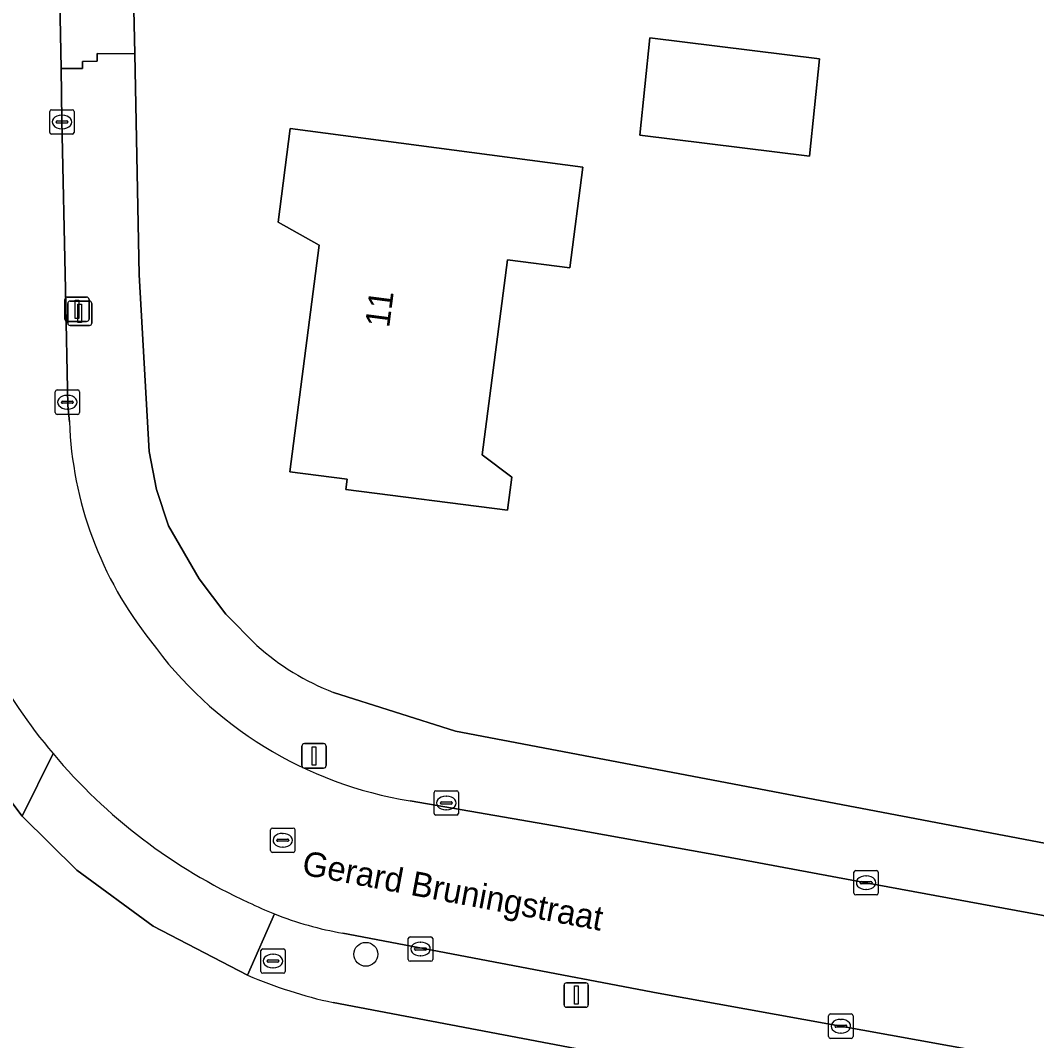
# Model space of a CAD drawing. Extents: x 161258 to 161838, y 380833 to 381727.
# Drawn here: x 161655.94 to 161697.58, y 381153.12 to 381194.91 of the extents above; entities that cross this region are included whole.
import ezdxf

# ---------------------------------------------------------------- set-up
doc = ezdxf.new("R2010")
doc.units = 0
for name, color, linetype in [('IMGEO_Boom', 7, 'Continuous'), ('IMGEO_Brandkraan', 7, 'Continuous'), ('IMGEO_Erf', 7, 'Continuous'), ('IMGEO_Kolk', 7, 'Continuous'), ('IMGEO_Lichtmast', 7, 'Continuous'), ('IMGEO_Openbare_ruimte_label', 7, 'Continuous'), ('IMGEO_Pand', 7, 'Continuous'), ('IMGEO_Pand_nummerreeks', 7, 'Continuous'), ('IMGEO_Rijbaan_lokaal_open', 7, 'Continuous'), ('IMGEO_Rioolput', 7, 'Continuous'), ('IMGEO_Voetpad_open', 7, 'Continuous')]:
    doc.layers.add(name, color=color, linetype=linetype)

msp = doc.modelspace()

# ---------------------------------------------------------------- linework, layer by layer
at = {"layer": 'IMGEO_Boom'}
msp.add_circle((161670.093, 381156.658), 0.489, dxfattribs=at)
at = {"layer": 'IMGEO_Brandkraan'}
for p, q in [((161665.79, 381155.956), (161665.79, 381156.808)), ((161665.865, 381156.882), (161666.717, 381156.882)), ((161666.278, 381156.662), (161666.303, 381156.662)), ((161666.791, 381156.808), (161666.791, 381155.956)), ((161666.049, 381156.376), (161666.049, 381156.388)), ((161666.487, 381156.339), (161666.089, 381156.339)), ((161666.092, 381156.425), (161666.49, 381156.425)), ((161666.533, 381156.388), (161666.533, 381156.376)), ((161666.717, 381155.882), (161665.865, 381155.882)), ((161666.301, 381156.102), (161666.276, 381156.102))]:
    msp.add_line(p, q, dxfattribs=at)
for points in [[(161665.79, 381155.956), (161665.79, 381156.808)], [(161665.865, 381156.882), (161666.717, 381156.882)], [(161666.791, 381156.808), (161666.791, 381155.956)], [(161666.717, 381155.882), (161665.865, 381155.882)]]:
    msp.add_lwpolyline(points, dxfattribs=at)
for centre, radius, start, end in [((161665.867, 381156.806), 0.0765, 91.552, 178.448), ((161665.867, 381156.806), 0.0765, 91.552, 178.448), ((161666.715, 381156.806), 0.0765, 1.552, 88.448), ((161666.715, 381156.806), 0.0765, 1.552, 88.448), ((161666.089, 381156.385), 0.0403, 85.8775, 175.7526), ((161666.086, 381156.375), 0.0366, 178.938, 274.7102), ((161666.49, 381156.382), 0.043, 264.8664, 352.4533), ((161666.494, 381156.387), 0.0386, 1.7309, 96.639), ((161665.867, 381155.958), 0.0765, 181.552, 268.448), ((161665.867, 381155.958), 0.0765, 181.552, 268.448), ((161666.715, 381155.958), 0.0765, 271.552, 358.448), ((161666.715, 381155.958), 0.0765, 271.552, 358.448)]:
    msp.add_arc(centre, radius, start, end, dxfattribs=at)
for centre, major_axis, ratio, start_param, end_param in [((161666.277, 381156.382), (-0.387, 0.002), 0.722429, 4.712389, 7.853982), ((161666.302, 381156.382), (-0.39, 0.002), 0.717154, 1.570796, 4.712389)]:
    msp.add_ellipse(centre, major_axis=major_axis, ratio=ratio, start_param=start_param, end_param=end_param, dxfattribs=at)
at = {"layer": 'IMGEO_Erf'}
for points in [[(161668.77, 381167.385), (161673.77, 381165.793), (161737.053, 381153.773), (161737.441, 381153.699), (161737.997, 381153.598), (161738.112, 381154.157), (161737.938, 381154.198), (161753.579, 381238.309), (161753.673, 381238.82), (161753.349, 381239.081), (161753.133, 381238.804), (161751.742, 381240.033), (161751.586, 381239.216), (161750.481, 381239.459), (161750.713, 381240.543), (161751.212, 381243.492), (161751.454, 381244.596), (161752.571, 381244.423), (161752.507, 381243.755), (161754.157, 381244.071), (161754.273, 381243.898), (161754.635, 381244.025), (161769.385, 381323.827)], [(161660.762, 381266.569), (161660.073, 381256.315), (161659.92, 381252.625), (161659.847, 381249.958), (161659.857, 381232.624), (161660.002, 381225.178), (161660.058, 381222.332), (161660.56, 381196.578), (161660.619, 381193.545), (161660.796, 381184.49), (161661.214, 381177.248), (161661.514, 381175.703), (161662, 381174.206), (161663.26, 381172.033), (161664.355, 381170.597), (161665.625, 381169.313)], [(161665.248, 381155.803), (161661.37, 381157.812), (161658.243, 381160.102), (161656.002, 381162.313), (161653.21, 381166.017)], [(161729.059, 381143.246), (161705.296, 381147.752), (161698.258, 381149.087), (161668.75, 381154.683)]]:
    msp.add_lwpolyline(points, dxfattribs=at)
for points in [[(161688.68, 381193.336), (161688.275, 381189.356), (161681.327, 381190.217), (161681.732, 381194.198)], [(161675.903, 381174.848), (161669.271, 381175.703), (161669.325, 381176.122), (161666.982, 381176.424), (161668.179, 381185.701), (161666.501, 381186.645), (161666.996, 381190.479), (161678.986, 381188.902), (161678.453, 381184.77), (161675.892, 381185.1), (161674.863, 381177.122), (161676.077, 381176.196)]]:
    msp.add_lwpolyline(points, close=True, dxfattribs=at)
for centre, radius, start, end in [((161672.457, 381176.928), 10.23, 228.1033, 248.877), ((161672.604, 381172.77), 18.493, 246.5596, 257.97)]:
    msp.add_arc(centre, radius, start, end, dxfattribs=at)
at = {"layer": 'IMGEO_Kolk'}
for p, q in [((161657.138, 381190.326), (161657.138, 381191.178)), ((161657.213, 381191.252), (161658.065, 381191.252)), ((161657.626, 381191.032), (161657.651, 381191.032)), ((161658.139, 381191.178), (161658.139, 381190.326)), ((161657.397, 381190.746), (161657.397, 381190.758)), ((161657.835, 381190.709), (161657.437, 381190.709)), ((161657.44, 381190.795), (161657.838, 381190.795)), ((161657.881, 381190.758), (161657.881, 381190.746)), ((161658.065, 381190.252), (161657.213, 381190.252)), ((161657.649, 381190.472), (161657.624, 381190.472)), ((161657.361, 381178.847), (161657.361, 381179.699)), ((161657.436, 381179.773), (161658.288, 381179.773)), ((161658.362, 381179.699), (161658.362, 381178.847)), ((161657.62, 381179.267), (161657.62, 381179.279)), ((161658.058, 381179.23), (161657.66, 381179.23)), ((161657.663, 381179.316), (161658.061, 381179.316)), ((161657.849, 381179.553), (161657.874, 381179.553)), ((161658.104, 381179.279), (161658.104, 381179.267)), ((161657.872, 381178.993), (161657.847, 381178.993)), ((161658.288, 381178.773), (161657.436, 381178.773)), ((161672.965, 381163.357), (161673.817, 381163.357)), ((161672.89, 381162.431), (161672.89, 381163.283)), ((161673.378, 381163.137), (161673.403, 381163.137)), ((161673.891, 381163.283), (161673.891, 381162.431)), ((161673.149, 381162.851), (161673.149, 381162.863)), ((161673.587, 381162.814), (161673.189, 381162.814)), ((161673.192, 381162.9), (161673.59, 381162.9)), ((161673.401, 381162.577), (161673.376, 381162.577)), ((161673.633, 381162.863), (161673.633, 381162.851)), ((161673.817, 381162.357), (161672.965, 381162.357)), ((161690.094, 381159.165), (161690.094, 381160.017)), ((161690.169, 381160.091), (161691.021, 381160.091)), ((161691.095, 381160.017), (161691.095, 381159.165)), ((161690.353, 381159.585), (161690.353, 381159.597)), ((161690.396, 381159.634), (161690.794, 381159.634)), ((161690.582, 381159.871), (161690.607, 381159.871)), ((161690.837, 381159.597), (161690.837, 381159.585)), ((161690.791, 381159.548), (161690.393, 381159.548)), ((161690.605, 381159.311), (161690.58, 381159.311)), ((161691.021, 381159.091), (161690.169, 381159.091)), ((161671.833, 381156.448), (161671.833, 381157.3)), ((161671.908, 381157.374), (161672.76, 381157.374)), ((161672.321, 381157.154), (161672.346, 381157.154)), ((161672.834, 381157.3), (161672.834, 381156.448)), ((161672.092, 381156.868), (161672.092, 381156.88)), ((161672.53, 381156.831), (161672.132, 381156.831)), ((161672.135, 381156.917), (161672.533, 381156.917)), ((161672.576, 381156.88), (161672.576, 381156.868)), ((161672.76, 381156.374), (161671.908, 381156.374)), ((161672.344, 381156.594), (161672.319, 381156.594)), ((161689.134, 381154.214), (161689.986, 381154.214)), ((161689.059, 381153.288), (161689.059, 381154.14)), ((161689.361, 381153.757), (161689.759, 381153.757)), ((161689.547, 381153.994), (161689.572, 381153.994)), ((161690.06, 381154.14), (161690.06, 381153.288)), ((161689.318, 381153.708), (161689.318, 381153.72)), ((161689.756, 381153.671), (161689.358, 381153.671)), ((161689.57, 381153.434), (161689.545, 381153.434)), ((161689.802, 381153.72), (161689.802, 381153.708)), ((161689.986, 381153.214), (161689.134, 381153.214))]:
    msp.add_line(p, q, dxfattribs=at)
for points in [[(161657.138, 381190.326), (161657.138, 381191.178)], [(161657.213, 381191.252), (161658.065, 381191.252)], [(161658.139, 381191.178), (161658.139, 381190.326)], [(161658.065, 381190.252), (161657.213, 381190.252)], [(161657.361, 381178.847), (161657.361, 381179.699)], [(161657.436, 381179.773), (161658.288, 381179.773)], [(161658.362, 381179.699), (161658.362, 381178.847)], [(161658.288, 381178.773), (161657.436, 381178.773)], [(161672.965, 381163.357), (161673.817, 381163.357)], [(161672.89, 381162.431), (161672.89, 381163.283)], [(161673.891, 381163.283), (161673.891, 381162.431)], [(161673.817, 381162.357), (161672.965, 381162.357)], [(161690.094, 381159.165), (161690.094, 381160.017)], [(161690.169, 381160.091), (161691.021, 381160.091)], [(161691.095, 381160.017), (161691.095, 381159.165)], [(161691.021, 381159.091), (161690.169, 381159.091)], [(161671.833, 381156.448), (161671.833, 381157.3)], [(161671.908, 381157.374), (161672.76, 381157.374)], [(161672.834, 381157.3), (161672.834, 381156.448)], [(161672.76, 381156.374), (161671.908, 381156.374)], [(161689.134, 381154.214), (161689.986, 381154.214)], [(161689.059, 381153.288), (161689.059, 381154.14)], [(161690.06, 381154.14), (161690.06, 381153.288)], [(161689.986, 381153.214), (161689.134, 381153.214)]]:
    msp.add_lwpolyline(points, dxfattribs=at)
for centre, radius, start, end in [((161657.215, 381191.176), 0.0765, 91.552, 178.448), ((161657.215, 381191.176), 0.0765, 91.552, 178.448), ((161658.063, 381191.176), 0.0765, 1.552, 88.448), ((161658.063, 381191.176), 0.0765, 1.552, 88.448), ((161657.437, 381190.755), 0.0403, 85.8775, 175.7526), ((161657.434, 381190.745), 0.0366, 178.938, 274.7102), ((161657.838, 381190.752), 0.043, 264.8664, 352.4533), ((161657.842, 381190.757), 0.0386, 1.7309, 96.639), ((161657.215, 381190.328), 0.0765, 181.552, 268.448), ((161657.215, 381190.328), 0.0765, 181.552, 268.448), ((161658.063, 381190.328), 0.0765, 271.552, 358.448), ((161658.063, 381190.328), 0.0765, 271.552, 358.448), ((161657.438, 381179.697), 0.0765, 91.552, 178.448), ((161657.438, 381179.697), 0.0765, 91.552, 178.448), ((161658.286, 381179.697), 0.0765, 1.552, 88.448), ((161658.286, 381179.697), 0.0765, 1.552, 88.448), ((161657.66, 381179.276), 0.0403, 85.8775, 175.7526), ((161657.657, 381179.266), 0.0366, 178.938, 274.7102), ((161658.061, 381179.273), 0.043, 264.8664, 352.4533), ((161658.065, 381179.278), 0.0386, 1.7309, 96.639), ((161657.438, 381178.849), 0.0765, 181.552, 268.448), ((161657.438, 381178.849), 0.0765, 181.552, 268.448), ((161658.286, 381178.849), 0.0765, 271.552, 358.448), ((161658.286, 381178.849), 0.0765, 271.552, 358.448), ((161672.967, 381163.281), 0.0765, 91.552, 178.448), ((161672.967, 381163.281), 0.0765, 91.552, 178.448), ((161673.815, 381163.281), 0.0765, 1.552, 88.448), ((161673.815, 381163.281), 0.0765, 1.552, 88.448), ((161673.189, 381162.86), 0.0403, 85.8775, 175.7526), ((161673.186, 381162.85), 0.0366, 178.938, 274.7102), ((161673.59, 381162.857), 0.043, 264.8664, 352.4533), ((161673.594, 381162.862), 0.0386, 1.7309, 96.639), ((161672.967, 381162.433), 0.0765, 181.552, 268.448), ((161672.967, 381162.433), 0.0765, 181.552, 268.448), ((161673.815, 381162.433), 0.0765, 271.552, 358.448), ((161673.815, 381162.433), 0.0765, 271.552, 358.448), ((161690.171, 381160.015), 0.0765, 91.552, 178.448), ((161690.171, 381160.015), 0.0765, 91.552, 178.448), ((161691.019, 381160.015), 0.0765, 1.552, 88.448), ((161691.019, 381160.015), 0.0765, 1.552, 88.448), ((161690.393, 381159.594), 0.0403, 85.8775, 175.7526), ((161690.39, 381159.584), 0.0366, 178.938, 274.7102), ((161690.794, 381159.591), 0.043, 264.8664, 352.4533), ((161690.798, 381159.596), 0.0386, 1.7309, 96.639), ((161690.171, 381159.167), 0.0765, 181.552, 268.448), ((161690.171, 381159.167), 0.0765, 181.552, 268.448), ((161691.019, 381159.167), 0.0765, 271.552, 358.448), ((161691.019, 381159.167), 0.0765, 271.552, 358.448), ((161671.91, 381157.298), 0.0765, 91.552, 178.448), ((161671.91, 381157.298), 0.0765, 91.552, 178.448), ((161672.758, 381157.298), 0.0765, 1.552, 88.448), ((161672.758, 381157.298), 0.0765, 1.552, 88.448), ((161672.132, 381156.877), 0.0403, 85.8775, 175.7526), ((161672.129, 381156.867), 0.0366, 178.938, 274.7102), ((161672.533, 381156.874), 0.043, 264.8664, 352.4533), ((161672.537, 381156.879), 0.0386, 1.7309, 96.639), ((161671.91, 381156.45), 0.0765, 181.552, 268.448), ((161671.91, 381156.45), 0.0765, 181.552, 268.448), ((161672.758, 381156.45), 0.0765, 271.552, 358.448), ((161672.758, 381156.45), 0.0765, 271.552, 358.448), ((161689.136, 381154.138), 0.0765, 91.552, 178.448), ((161689.136, 381154.138), 0.0765, 91.552, 178.448), ((161689.984, 381154.138), 0.0765, 1.552, 88.448), ((161689.984, 381154.138), 0.0765, 1.552, 88.448), ((161689.358, 381153.717), 0.0403, 85.8775, 175.7526), ((161689.763, 381153.719), 0.0386, 1.7309, 96.639), ((161689.355, 381153.707), 0.0366, 178.938, 274.7102), ((161689.759, 381153.714), 0.043, 264.8664, 352.4533), ((161689.136, 381153.29), 0.0765, 181.552, 268.448), ((161689.136, 381153.29), 0.0765, 181.552, 268.448), ((161689.984, 381153.29), 0.0765, 271.552, 358.448), ((161689.984, 381153.29), 0.0765, 271.552, 358.448)]:
    msp.add_arc(centre, radius, start, end, dxfattribs=at)
for centre, major_axis, ratio, start_param, end_param in [((161657.625, 381190.752), (-0.387, 0.002), 0.722429, 4.712389, 7.853982), ((161657.65, 381190.752), (-0.39, 0.002), 0.717154, 1.570796, 4.712389), ((161657.848, 381179.273), (-0.387, 0.002), 0.722429, 4.712389, 7.853982), ((161657.873, 381179.273), (-0.39, 0.002), 0.717154, 1.570796, 4.712389), ((161673.377, 381162.857), (-0.387, 0.002), 0.722429, 4.712389, 7.853982), ((161673.402, 381162.857), (-0.39, 0.002), 0.717154, 1.570796, 4.712389), ((161690.581, 381159.591), (-0.387, 0.002), 0.722429, 4.712389, 7.853982), ((161690.606, 381159.591), (-0.39, 0.002), 0.717154, 1.570796, 4.712389), ((161672.32, 381156.874), (-0.387, 0.002), 0.722429, 4.712389, 7.853982), ((161672.345, 381156.874), (-0.39, 0.002), 0.717154, 1.570796, 4.712389), ((161689.546, 381153.714), (-0.387, 0.002), 0.722429, 4.712389, 7.853982), ((161689.571, 381153.714), (-0.39, 0.002), 0.717154, 1.570796, 4.712389)]:
    msp.add_ellipse(centre, major_axis=major_axis, ratio=ratio, start_param=start_param, end_param=end_param, dxfattribs=at)
at = {"layer": 'IMGEO_Lichtmast'}
for p, q in [((161657.757, 381182.678), (161657.757, 381183.478)), ((161657.757, 381183.478), (161657.757, 381182.678)), ((161657.857, 381183.578), (161658.647, 381183.578)), ((161658.647, 381183.578), (161657.857, 381183.578)), ((161657.973, 381183.414), (161658.763, 381183.414)), ((161658.763, 381183.414), (161657.973, 381183.414)), ((161658.747, 381183.478), (161658.747, 381182.678)), ((161658.747, 381182.678), (161658.747, 381183.478)), ((161657.873, 381182.514), (161657.873, 381183.314)), ((161657.873, 381183.314), (161657.873, 381182.514)), ((161658.863, 381183.314), (161658.863, 381182.514)), ((161658.863, 381182.514), (161658.863, 381183.314)), ((161658.647, 381182.578), (161657.857, 381182.578)), ((161657.857, 381182.578), (161658.647, 381182.578)), ((161658.763, 381182.414), (161657.973, 381182.414)), ((161657.973, 381182.414), (161658.763, 381182.414)), ((161667.472, 381164.387), (161667.472, 381165.187)), ((161667.472, 381165.187), (161667.472, 381164.387)), ((161667.572, 381165.287), (161668.362, 381165.287)), ((161668.362, 381165.287), (161667.572, 381165.287)), ((161668.462, 381165.187), (161668.462, 381164.387)), ((161668.462, 381164.387), (161668.462, 381165.187)), ((161668.362, 381164.287), (161667.572, 381164.287)), ((161667.572, 381164.287), (161668.362, 381164.287)), ((161678.319, 381155.49), (161679.109, 381155.49)), ((161679.109, 381155.49), (161678.319, 381155.49)), ((161678.219, 381154.59), (161678.219, 381155.39)), ((161678.219, 381155.39), (161678.219, 381154.59)), ((161679.209, 381155.39), (161679.209, 381154.59)), ((161679.209, 381154.59), (161679.209, 381155.39)), ((161679.109, 381154.49), (161678.319, 381154.49)), ((161678.319, 381154.49), (161679.109, 381154.49))]:
    msp.add_line(p, q, dxfattribs=at)
for points in [[(161658.177, 381183.453), (161658.327, 381183.453), (161658.327, 381182.703), (161658.177, 381182.703), (161658.177, 381183.453)], [(161658.293, 381183.289), (161658.443, 381183.289), (161658.443, 381182.539), (161658.293, 381182.539), (161658.293, 381183.289)], [(161667.892, 381165.162), (161668.042, 381165.162), (161668.042, 381164.412), (161667.892, 381164.412), (161667.892, 381165.162)], [(161678.639, 381155.365), (161678.789, 381155.365), (161678.789, 381154.615), (161678.639, 381154.615), (161678.639, 381155.365)]]:
    msp.add_lwpolyline(points, dxfattribs=at)
for centre, start, end in [((161657.857, 381183.478), 90, 180), ((161657.857, 381183.478), 90, 180), ((161657.973, 381183.314), 90, 180), ((161657.973, 381183.314), 90, 180), ((161658.647, 381183.478), 0, 90), ((161658.647, 381183.478), 360, 90), ((161658.763, 381183.314), 0, 90), ((161658.763, 381183.314), 360, 90), ((161657.857, 381182.678), 180, 270), ((161657.857, 381182.678), 180, 270), ((161658.647, 381182.678), 270, 0), ((161658.647, 381182.678), 270, 0), ((161657.973, 381182.514), 180, 270), ((161657.973, 381182.514), 180, 270), ((161658.763, 381182.514), 270, 0), ((161658.763, 381182.514), 270, 0), ((161667.572, 381165.187), 90, 180), ((161667.572, 381165.187), 90, 180), ((161668.362, 381165.187), 0, 90), ((161668.362, 381165.187), 360, 90), ((161667.572, 381164.387), 180, 270), ((161667.572, 381164.387), 180, 270), ((161668.362, 381164.387), 270, 0), ((161668.362, 381164.387), 270, 0), ((161678.319, 381155.39), 90, 180), ((161678.319, 381155.39), 90, 180), ((161679.109, 381155.39), 0, 90), ((161679.109, 381155.39), 360, 90), ((161678.319, 381154.59), 180, 270), ((161678.319, 381154.59), 180, 270), ((161679.109, 381154.59), 270, 0), ((161679.109, 381154.59), 270, 0)]:
    msp.add_arc(centre, 0.1, start, end, dxfattribs=at)
at = {"layer": 'IMGEO_Pand'}
for points in [[(161681.732, 381194.198), (161681.327, 381190.217), (161688.275, 381189.356), (161688.68, 381193.336)], [(161675.903, 381174.848), (161676.077, 381176.196), (161674.863, 381177.122), (161675.892, 381185.1), (161678.453, 381184.77), (161678.986, 381188.902), (161666.996, 381190.479), (161666.501, 381186.645), (161668.179, 381185.701), (161666.982, 381176.424), (161669.325, 381176.122), (161669.271, 381175.703)]]:
    msp.add_lwpolyline(points, close=True, dxfattribs=at)
at = {"layer": 'IMGEO_Rijbaan_lokaal_open'}
for points in [[(161657.941, 381178.467), (161657.878, 381179.14), (161657.784, 381183.884), (161657.637, 381190.821), (161657.6, 381192.937), (161657.527, 381197.132), (161657.496, 381198.896), (161657.016, 381221.388), (161656.949, 381224.532), (161656.9, 381226.01), (161656.661, 381233.168), (161656.633, 381235.807), (161656.639, 381237.026), (161656.634, 381242.223), (161656.651, 381245.83), (161656.712, 381249.982), (161656.8, 381253.735)], [(161669.154, 381157.523), (161682.076, 381155.063), (161697.566, 381152.273), (161698.283, 381152.136), (161706.149, 381150.632), (161710.948, 381149.714), (161728.168, 381146.455), (161735.396, 381145.088), (161735.76, 381147.064), (161736.147, 381148.935), (161736.521, 381150.931), (161729.309, 381152.304), (161712.607, 381155.438), (161707.169, 381156.459), (161706.789, 381156.53), (161698.673, 381158.104), (161690.593, 381159.591), (161684.811, 381160.667), (161677.82, 381161.927), (161671.905, 381162.945)]]:
    msp.add_lwpolyline(points, dxfattribs=at)
for centre, radius, start, end in [((161673.225, 381179.038), 15.294, 182.1378, 218.5647), ((161674.848, 381179.665), 22.969, 196.8701, 220.0766), ((161674.483, 381179.037), 16.297, 215.8028, 260.8969), ((161674.827, 381179.644), 22.939, 220.0717, 245.4118), ((161671.705, 381171.856), 14.564, 243.8331, 248.4119), ((161671.634, 381171.707), 14.4, 248.4538, 260.0816)]:
    msp.add_arc(centre, radius, start, end, dxfattribs=at)
at = {"layer": 'IMGEO_Rioolput'}
for p, q in [((161666.188, 381160.904), (161666.188, 381161.756)), ((161666.263, 381161.83), (161667.115, 381161.83)), ((161667.189, 381161.756), (161667.189, 381160.904)), ((161666.447, 381161.324), (161666.447, 381161.336)), ((161666.885, 381161.287), (161666.487, 381161.287)), ((161666.49, 381161.373), (161666.888, 381161.373)), ((161666.676, 381161.61), (161666.701, 381161.61)), ((161666.931, 381161.336), (161666.931, 381161.324)), ((161667.115, 381160.83), (161666.263, 381160.83)), ((161666.699, 381161.05), (161666.674, 381161.05))]:
    msp.add_line(p, q, dxfattribs=at)
for points in [[(161666.188, 381160.904), (161666.188, 381161.756)], [(161666.263, 381161.83), (161667.115, 381161.83)], [(161667.189, 381161.756), (161667.189, 381160.904)], [(161667.115, 381160.83), (161666.263, 381160.83)]]:
    msp.add_lwpolyline(points, dxfattribs=at)
for centre, radius, start, end in [((161666.265, 381161.754), 0.0765, 91.552, 178.448), ((161666.265, 381161.754), 0.0765, 91.552, 178.448), ((161667.113, 381161.754), 0.0765, 1.552, 88.448), ((161667.113, 381161.754), 0.0765, 1.552, 88.448), ((161666.487, 381161.333), 0.0403, 85.8775, 175.7526), ((161666.484, 381161.323), 0.0366, 178.938, 274.7102), ((161666.888, 381161.33), 0.043, 264.8664, 352.4533), ((161666.892, 381161.335), 0.0386, 1.7309, 96.639), ((161666.265, 381160.906), 0.0765, 181.552, 268.448), ((161666.265, 381160.906), 0.0765, 181.552, 268.448), ((161667.113, 381160.906), 0.0765, 271.552, 358.448), ((161667.113, 381160.906), 0.0765, 271.552, 358.448)]:
    msp.add_arc(centre, radius, start, end, dxfattribs=at)
for centre, major_axis, ratio, start_param, end_param in [((161666.675, 381161.33), (-0.387, 0.002), 0.722429, 4.712389, 7.853982), ((161666.7, 381161.33), (-0.39, 0.002), 0.717154, 1.570796, 4.712389)]:
    msp.add_ellipse(centre, major_axis=major_axis, ratio=ratio, start_param=start_param, end_param=end_param, dxfattribs=at)
at = {"layer": 'IMGEO_Voetpad_open'}
msp.add_lwpolyline([(161660.56, 381196.578), (161658.664, 381196.553), (161658.659, 381196.829), (161658.385, 381196.841), (161658.374, 381197.131), (161657.527, 381197.132), (161657.6, 381192.937), (161658.485, 381192.937), (161658.485, 381193.235), (161659.075, 381193.245), (161659.075, 381193.553), (161660.619, 381193.545)], close=True, dxfattribs=at)
for points in [[(161665.625, 381169.313), (161664.355, 381170.597), (161663.26, 381172.033), (161662, 381174.206), (161661.514, 381175.703), (161661.214, 381177.248), (161660.796, 381184.49), (161660.619, 381193.545), (161659.075, 381193.553), (161659.075, 381193.245), (161658.485, 381193.235), (161658.485, 381192.937), (161657.6, 381192.937), (161657.637, 381190.821), (161657.784, 381183.884), (161657.878, 381179.14), (161657.941, 381178.467)], [(161673.77, 381165.793), (161668.77, 381167.385)], [(161653.21, 381166.017), (161656.002, 381162.313), (161657.273, 381164.877)], [(161671.905, 381162.945), (161677.82, 381161.927), (161684.811, 381160.667), (161690.593, 381159.591), (161698.673, 381158.104), (161706.789, 381156.53), (161707.169, 381156.459), (161712.607, 381155.438), (161729.309, 381152.304), (161736.521, 381150.931), (161737.053, 381153.773), (161673.77, 381165.793)], [(161657.273, 381164.877), (161656.002, 381162.313), (161658.243, 381160.102), (161661.37, 381157.812), (161665.248, 381155.803), (161666.346, 381158.314)], [(161666.346, 381158.314), (161665.248, 381155.803)], [(161682.076, 381155.063), (161669.154, 381157.523)], [(161668.75, 381154.683), (161698.258, 381149.087), (161698.283, 381152.136), (161697.566, 381152.273), (161682.076, 381155.063)]]:
    msp.add_lwpolyline(points, dxfattribs=at)
for centre, radius, start, end in [((161673.225, 381179.038), 15.294, 182.1378, 218.5647), ((161674.848, 381179.665), 22.969, 196.8701, 220.0766), ((161674.483, 381179.037), 16.297, 215.8028, 260.8969), ((161672.457, 381176.928), 10.23, 228.1033, 248.877), ((161674.827, 381179.644), 22.939, 220.0717, 245.4118), ((161671.705, 381171.856), 14.564, 243.8331, 248.4119), ((161671.634, 381171.707), 14.4, 248.4538, 260.0816), ((161672.604, 381172.77), 18.493, 246.5596, 257.97)]:
    msp.add_arc(centre, radius, start, end, dxfattribs=at)

# ---------------------------------------------------------------- texts
at = {"layer": 'IMGEO_Openbare_ruimte_label'}
msp.add_text('Gerard Bruningstraat', height=1, rotation=349.3416, dxfattribs=at).set_placement((161667.431, 381159.933))
at = {"layer": 'IMGEO_Pand_nummerreeks'}
msp.add_text('11', height=1, rotation=82.6478, dxfattribs=at).set_placement((161671.047, 381182.299))

doc.saveas('drawing.dxf')
